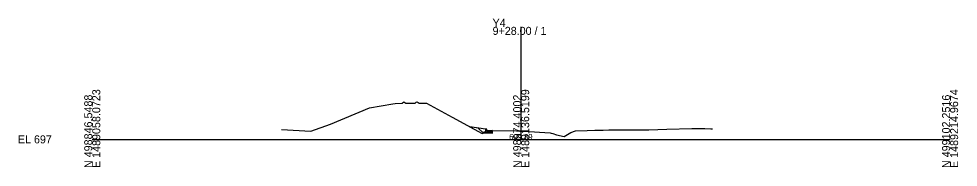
# Model space of a CAD drawing. Extents: x -26 to 1489054, y -10 to 499098.
# Drawn here: x 2774.3 to 3102.8, y -9.7 to 42 of the extents above; entities that cross this region are included whole.
import ezdxf

# ---------------------------------------------------------------- set-up
doc = ezdxf.new("R2010")
doc.units = 0
for name, color, linetype in [('Exist Cross Section Cell', 7, 'Continuous'), ('Exist XS Center Line Elevation Label', 7, 'Continuous'), ('Exist XS Ground Line', 7, 'Continuous'), ('Prop CMT Conc Surface', 7, 'Continuous'), ('Prop CMT Concrete Structures', 7, 'Continuous'), ('Prop CMT Pvmt Course 1 CG', 7, 'Continuous'), ('Prop CMT Slope Grass', 7, 'Continuous'), ('Prop CMT Subgrade Earthwork', 7, 'Continuous'), ('Prop XS Earthwork Shape', 7, 'Continuous'), ('Scratch_Level_1', 7, 'Continuous')]:
    doc.layers.add(name, color=color, linetype=linetype)

msp = doc.modelspace()

# ---------------------------------------------------------------- linework, layer by layer
at = {"layer": 'Exist Cross Section Cell'}
for p, q in [((2950, 0), (2950, 39.25)), ((2800, 0), (2950, 0)), ((2950, 0), (3100, 0))]:
    msp.add_line(p, q, dxfattribs=at)
at = {"layer": 'Exist XS Ground Line'}
msp.add_lwpolyline([(2866.2, 3.45), (2876.48, 2.88), (2883.37, 5.3), (2896.96, 10.98), (2905.06, 12.41), (2905.91, 12.57), (2908.35, 12.59), (2908.94, 13.07), (2909.66, 12.6), (2909.96, 12.61), (2912.9, 12.64), (2913.29, 12.93), (2913.64, 13.08), (2914.35, 12.65), (2914.96, 12.66), (2916.86, 12.67), (2925.91, 7.73), (2936.33, 2.09), (2938.29, 2.72), (2938.85, 2.83), (2939.39, 2.96), (2939.97, 3.09), (2948.33, 2.95), (2949.56, 2.91), (2950, 2.89), (2950.97, 2.82), (2960.12, 2.25), (2960.53, 2.12), (2961.12, 2.02), (2962.38, 1.59), (2965.02, 0.99), (2967.31, 2.39), (2969.01, 2.98), (2973.08, 3.11), (2975.79, 3.2), (2978.63, 3.27), (2980.64, 3.31), (2991.13, 3.32), (2994.65, 3.37), (3000.95, 3.53), (3009.72, 3.79), (3010.87, 3.79), (3012.79, 3.8), (3014.25, 3.79), (3016.27, 3.7), (3016.87, 3.65)], dxfattribs=at)
at = {"layer": 'Prop CMT Conc Surface'}
for points in [[(2937.97, 3.02), (2937.97, 3.52), (2937.47, 3.52)], [(2939.97, 3.09), (2937.97, 3.02)]]:
    msp.add_lwpolyline(points, dxfattribs=at)
at = {"layer": 'Prop CMT Concrete Structures'}
for points in [[(2939.97, 3.09), (2937.97, 3.02), (2937.97, 3.52), (2937.47, 3.52)], [(2937.47, 3.52), (2937.47, 2.52), (2939.97, 2.5)], [(2939.97, 2.5), (2939.97, 3.09)]]:
    msp.add_lwpolyline(points, dxfattribs=at)
at = {"layer": 'Prop CMT Pvmt Course 1 CG'}
for points in [[(2939.97, 2.5), (2936.97, 2.52), (2936.68, 2.23)], [(2936.68, 2.23), (2939.97, 2.21)], [(2939.97, 2.21), (2939.97, 2.5)]]:
    msp.add_lwpolyline(points, dxfattribs=at)
at = {"layer": 'Prop CMT Slope Grass'}
msp.add_line((2937.47, 3.52), (2932, 4.43), dxfattribs=at)
at = {"layer": 'Prop CMT Subgrade Earthwork'}
msp.add_line((2939.97, 2.21), (2939.97, 3.09), dxfattribs=at)
msp.add_lwpolyline([(2939.97, 2.21), (2936.68, 2.23), (2934.97, 3.93)], dxfattribs=at)
at = {"layer": 'Prop XS Earthwork Shape'}
for points in [[(2934.97, 3.93), (2932, 4.43), (2936.33, 2.09), (2936.79, 2.23), (2936.68, 2.23)], [(2939.97, 2.21), (2939.97, 3.09), (2939.39, 2.96), (2938.85, 2.83), (2938.29, 2.72), (2936.79, 2.23)]]:
    msp.add_lwpolyline(points, close=True, dxfattribs=at)

# ---------------------------------------------------------------- texts
at = {"layer": 'Exist Cross Section Cell'}
for s, p in [('Y4', (2940, 39.25)), ('9+28.00 / 1', (2940, 36.45)), ('EL 697', (2774, -1.4))]:
    msp.add_text(s, height=2.8, dxfattribs=at).set_placement(p)
for s, p in [('E 1489058.0723', (2802.8, -10)), ('E 1489136.5199', (2952.8, -10)), ('E 1489214.9674', (3102.8, -10)), ('N 498846.5488', (2800, -10)), ('N 498974.4002', (2950, -10)), ('N 499102.2516', (3100, -10))]:
    msp.add_text(s, height=2.8, rotation=90, dxfattribs=at).set_placement(p)
at = {"layer": 'Exist XS Center Line Elevation Label'}
msp.add_text('699.89', height=2, dxfattribs=at).set_placement((2945.81, -0.11))
at = {"layer": 'Scratch_Level_1'}
for s, p in [('LT_CG_Top_BOC', (2937.35, 3.51)), ('LT_CG_Top_Face', (2937.84, 3.51)), ('LT_Sub_OEOP', (2936.58, 2.22)), ('LT_CG1_Shelf_Out', (2936.83, 2.51)), ('LT_CG_Bot_BOC', (2937.35, 2.51)), ('LT_CG_Top_Gut', (2937.85, 3.01))]:
    msp.add_text(s, height=0.02, dxfattribs=at).set_placement(p)

doc.saveas('drawing.dxf')
